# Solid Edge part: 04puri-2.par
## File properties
Username: User
Author: User
Template: Iso Metric Part.par
Last saved by: User
Revision: 4
Application: Solid Edge
Accuracy: 0,990
Face Style: Model Default
Fill Style: Normal
Coef. of Thermal Exp: 0.0
Thermal Conductivity: 0.0
Specific Heat: 0.0
Modulus of Elasticity: 0.0
Poisson's Ratio: 0.0
Yield Stress: 0.0
Ultimate Stress: 0.0
Elongation: 0.0
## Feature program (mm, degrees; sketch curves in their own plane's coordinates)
thicken "unnamed Thicken 1"
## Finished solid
Body 1: solid body, 5 faces, 9 edges, 6 vertices.
  Faces by surface: spline 4, offset 1
  Edges by curve: curve on surface 9
Body 2: sheet body, 1 face, 3 edges, 3 vertices.
  Faces by surface: spline 1
  Edges by curve: curve on surface 3
Bounding box of the edges (mm; curved faces can reach further): 144.647 x 68.253 x 208.768, from (-119.137, -0.0003, 53.1203) to (25.5104, 68.2529, 261.8878).
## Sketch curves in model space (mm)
spline (12.0291, 38.1792, 53.4192) -> (24.7003, 65.9963, 159.1608) -> (-5.3623, 0, 261.5905)
spline (-118.7215, 0, 53.4192) -> (-74.7666, 0, 182.6096) -> (-5.3623, 0, 261.5905)
spline (-118.7215, 0, 53.4192) -> (-52.4096, 42.1699, 53.4192) -> (12.0291, 38.1792, 53.4192)
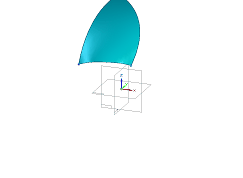
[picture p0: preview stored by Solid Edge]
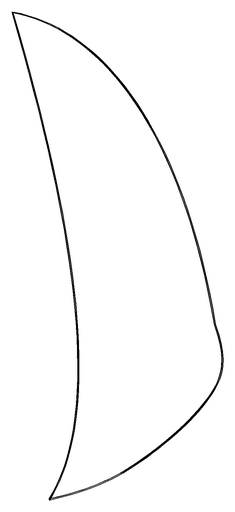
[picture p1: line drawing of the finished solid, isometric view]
